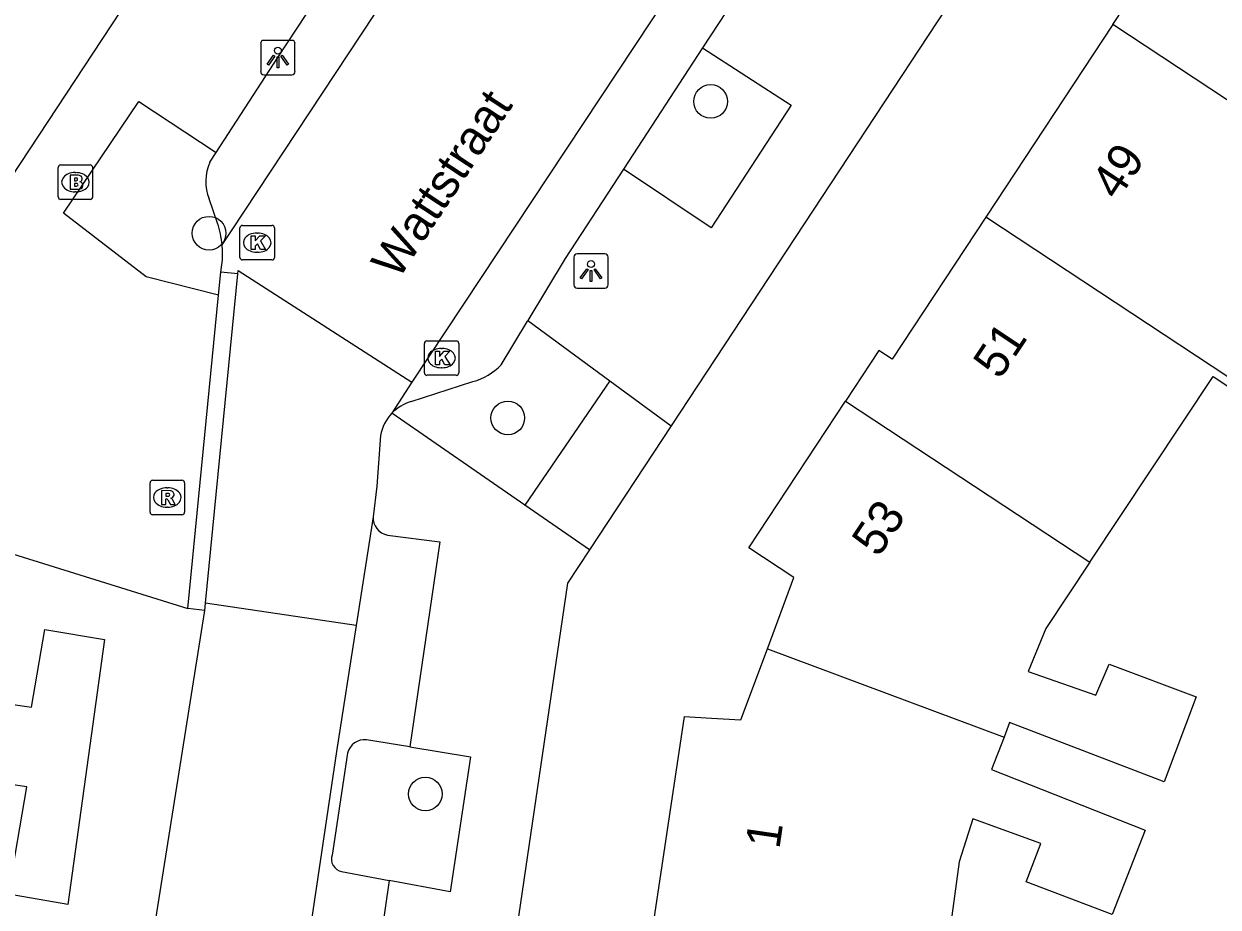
# Model space of a CAD drawing. Extents: x 159280 to 160375, y 384531 to 385872.
# Drawn here: x 159980.04 to 160014.71, y 384791.65 to 384817.27 of the extents above; entities that cross this region are included whole.
import ezdxf

# ---------------------------------------------------------------- set-up
doc = ezdxf.new("R2010")
doc.units = 0
for name, color, linetype in [('IMGEO_Boom', 7, 'Continuous'), ('IMGEO_Brandkraan', 7, 'Continuous'), ('IMGEO_Kolk', 7, 'Continuous'), ('IMGEO_Lichtpunt', 7, 'Continuous'), ('IMGEO_Openbare_ruimte_label', 7, 'Continuous'), ('IMGEO_Pand', 7, 'Continuous'), ('IMGEO_Pand_nummerreeks', 7, 'Continuous'), ('IMGEO_Parkeervlak_open', 7, 'Continuous'), ('IMGEO_Rijbaan_lokaal_open', 7, 'Continuous'), ('IMGEO_Rioolput', 7, 'Continuous'), ('IMGEO_Voetpad_open', 7, 'Continuous')]:
    doc.layers.add(name, color=color, linetype=linetype)

msp = doc.modelspace()

# ---------------------------------------------------------------- linework, layer by layer
at = {"layer": 'IMGEO_Boom'}
for centre in [(159999.976, 384815.022), (159985.419, 384811.2), (159994.089, 384805.84), (159991.696, 384794.928)]:
    msp.add_circle(centre, 0.489, dxfattribs=at)
at = {"layer": 'IMGEO_Brandkraan'}
for p, q in [((159981.039, 384812.253), (159981.039, 384813.105)), ((159981.114, 384813.179), (159981.966, 384813.179)), ((159982.04, 384813.105), (159982.04, 384812.253)), ((159981.527, 384812.959), (159981.552, 384812.959)), ((159981.55, 384812.399), (159981.525, 384812.399)), ((159981.966, 384812.179), (159981.114, 384812.179))]:
    msp.add_line(p, q, dxfattribs=at)
for points in [[(159981.039, 384812.253), (159981.039, 384813.105)], [(159981.114, 384813.179), (159981.966, 384813.179)], [(159982.04, 384813.105), (159982.04, 384812.253)], [(159981.387, 384812.879), (159981.387, 384812.479), (159981.6, 384812.479)], [(159981.618, 384812.879), (159981.387, 384812.879)], [(159981.566, 384812.798), (159981.512, 384812.798), (159981.512, 384812.722)], [(159981.512, 384812.722), (159981.565, 384812.722)], [(159981.574, 384812.646), (159981.512, 384812.646), (159981.512, 384812.565)], [(159981.512, 384812.565), (159981.574, 384812.565)], [(159981.966, 384812.179), (159981.114, 384812.179)]]:
    msp.add_lwpolyline(points, dxfattribs=at)
for centre, radius, start, end in [((159981.116, 384813.103), 0.0765, 91.552, 178.448), ((159981.116, 384813.103), 0.0765, 91.552, 178.448), ((159981.964, 384813.103), 0.0765, 1.552, 88.448), ((159981.964, 384813.103), 0.0765, 1.552, 88.448), ((159981.567, 384812.76), 0.0379, 267.8285, 90.9355), ((159981.622, 384812.734), 0.145, 59.4692, 91.5367), ((159981.647, 384812.781), 0.0922, 285.5137, 58.1501), ((159981.652, 384812.589), 0.105, 301.3115, 78.989), ((159981.575, 384812.605), 0.0404, 269.8759, 90.5077), ((159981.606, 384812.73), 0.251, 268.6676, 293.5347), ((159981.116, 384812.255), 0.0765, 181.552, 268.448), ((159981.116, 384812.255), 0.0765, 181.552, 268.448), ((159981.964, 384812.255), 0.0765, 271.552, 358.448), ((159981.964, 384812.255), 0.0765, 271.552, 358.448)]:
    msp.add_arc(centre, radius, start, end, dxfattribs=at)
for centre, major_axis, ratio, start_param, end_param in [((159981.526, 384812.679), (-0.387, 0.002), 0.722429, 4.712389, 7.853982), ((159981.551, 384812.679), (-0.39, 0.002), 0.717154, 1.570796, 4.712389)]:
    msp.add_ellipse(centre, major_axis=major_axis, ratio=ratio, start_param=start_param, end_param=end_param, dxfattribs=at)
at = {"layer": 'IMGEO_Kolk'}
for p, q in [((159986.315, 384810.499), (159986.315, 384811.351)), ((159986.39, 384811.425), (159987.242, 384811.425)), ((159987.316, 384811.351), (159987.316, 384810.499)), ((159986.803, 384811.205), (159986.828, 384811.205)), ((159986.826, 384810.645), (159986.801, 384810.645)), ((159987.242, 384810.425), (159986.39, 384810.425)), ((159991.667, 384807.15), (159991.667, 384808.002)), ((159991.742, 384808.076), (159992.594, 384808.076)), ((159992.155, 384807.856), (159992.18, 384807.856)), ((159992.668, 384808.002), (159992.668, 384807.15)), ((159992.178, 384807.296), (159992.153, 384807.296)), ((159992.594, 384807.076), (159991.742, 384807.076))]:
    msp.add_line(p, q, dxfattribs=at)
for points in [[(159986.315, 384810.499), (159986.315, 384811.351)], [(159986.39, 384811.425), (159987.242, 384811.425)], [(159987.316, 384811.351), (159987.316, 384810.499)], [(159986.636, 384811.125), (159986.759, 384811.125), (159986.759, 384810.974), (159986.889, 384811.125), (159987.053, 384811.125), (159986.907, 384810.974), (159987.06, 384810.725), (159986.908, 384810.725), (159986.823, 384810.889), (159986.759, 384810.822), (159986.759, 384810.725), (159986.636, 384810.725), (159986.636, 384811.125)], [(159987.242, 384810.425), (159986.39, 384810.425)], [(159991.667, 384807.15), (159991.667, 384808.002)], [(159991.742, 384808.076), (159992.594, 384808.076)], [(159992.668, 384808.002), (159992.668, 384807.15)], [(159991.988, 384807.776), (159992.111, 384807.776), (159992.111, 384807.625), (159992.241, 384807.776), (159992.405, 384807.776), (159992.259, 384807.625), (159992.412, 384807.376), (159992.26, 384807.376), (159992.175, 384807.54), (159992.111, 384807.473), (159992.111, 384807.376), (159991.988, 384807.376), (159991.988, 384807.776)], [(159992.594, 384807.076), (159991.742, 384807.076)]]:
    msp.add_lwpolyline(points, dxfattribs=at)
for centre, start, end in [((159986.392, 384811.349), 91.552, 178.448), ((159986.392, 384811.349), 91.552, 178.448), ((159987.24, 384811.349), 1.552, 88.448), ((159987.24, 384811.349), 1.552, 88.448), ((159986.392, 384810.501), 181.552, 268.448), ((159986.392, 384810.501), 181.552, 268.448), ((159987.24, 384810.501), 271.552, 358.448), ((159987.24, 384810.501), 271.552, 358.448), ((159991.744, 384808), 91.552, 178.448), ((159991.744, 384808), 91.552, 178.448), ((159992.592, 384808), 1.552, 88.448), ((159992.592, 384808), 1.552, 88.448), ((159991.744, 384807.152), 181.552, 268.448), ((159991.744, 384807.152), 181.552, 268.448), ((159992.592, 384807.152), 271.552, 358.448), ((159992.592, 384807.152), 271.552, 358.448)]:
    msp.add_arc(centre, 0.0765, start, end, dxfattribs=at)
for centre, major_axis, ratio, start_param, end_param in [((159986.802, 384810.925), (-0.387, 0.002), 0.722429, 4.712389, 7.853982), ((159986.827, 384810.925), (-0.39, 0.002), 0.717154, 1.570796, 4.712389), ((159992.154, 384807.576), (-0.387, 0.002), 0.722429, 4.712389, 7.853982), ((159992.179, 384807.576), (-0.39, 0.002), 0.717154, 1.570796, 4.712389)]:
    msp.add_ellipse(centre, major_axis=major_axis, ratio=ratio, start_param=start_param, end_param=end_param, dxfattribs=at)
at = {"layer": 'IMGEO_Lichtpunt'}
for p, q in [((159986.917, 384816.7), (159986.917, 384815.893)), ((159986.917, 384816.7), (159986.917, 384815.893)), ((159987.819, 384816.795), (159987.011, 384816.795)), ((159987.819, 384816.795), (159987.011, 384816.795)), ((159987.913, 384815.893), (159987.913, 384816.7)), ((159987.913, 384815.893), (159987.913, 384816.7)), ((159987.011, 384815.799), (159987.819, 384815.799)), ((159987.011, 384815.799), (159987.819, 384815.799)), ((159996.908, 384810.601), (159996.1, 384810.601)), ((159996.908, 384810.601), (159996.1, 384810.601)), ((159996.006, 384810.506), (159996.006, 384809.699)), ((159996.006, 384810.506), (159996.006, 384809.699)), ((159997.002, 384809.699), (159997.002, 384810.506)), ((159997.002, 384809.699), (159997.002, 384810.506)), ((159996.1, 384809.605), (159996.908, 384809.605)), ((159996.1, 384809.605), (159996.908, 384809.605))]:
    msp.add_line(p, q, dxfattribs=at)
for points in [[(159987.291, 384816.364), (159987.33, 384816.336), (159987.142, 384816.074), (159987.104, 384816.101), (159987.291, 384816.364)], [(159987.393, 384816.316), (159987.44, 384816.316), (159987.44, 384815.994), (159987.393, 384815.994), (159987.393, 384816.316)], [(159987.503, 384816.336), (159987.541, 384816.363), (159987.728, 384816.101), (159987.689, 384816.073), (159987.503, 384816.336)], [(159996.38, 384810.17), (159996.419, 384810.142), (159996.231, 384809.88), (159996.193, 384809.907), (159996.38, 384810.17)], [(159996.482, 384810.122), (159996.529, 384810.122), (159996.529, 384809.8), (159996.482, 384809.8), (159996.482, 384810.122)], [(159996.592, 384810.142), (159996.63, 384810.169), (159996.817, 384809.907), (159996.778, 384809.879), (159996.592, 384810.142)]]:
    msp.add_lwpolyline(points, dxfattribs=at)
for centre in [(159987.416, 384816.498), (159996.505, 384810.304)]:
    msp.add_circle(centre, 0.0994, dxfattribs=at)
for centre, start, end in [((159987.011, 384816.7), 90, 180), ((159987.011, 384816.7), 90, 180), ((159987.819, 384816.7), 0, 90), ((159987.819, 384816.7), 0, 90), ((159987.011, 384815.893), 180, 270), ((159987.011, 384815.893), 180, 270), ((159987.819, 384815.893), 270, 0), ((159987.819, 384815.893), 270, 360), ((159996.1, 384810.506), 90, 180), ((159996.1, 384810.506), 90, 180), ((159996.908, 384810.506), 0, 90), ((159996.908, 384810.506), 0, 90), ((159996.1, 384809.699), 180, 270), ((159996.1, 384809.699), 180, 270), ((159996.908, 384809.699), 270, 0), ((159996.908, 384809.699), 270, 360)]:
    msp.add_arc(centre, 0.0946, start, end, dxfattribs=at)
at = {"layer": 'IMGEO_Pand'}
for points in [[(160011.647, 384817.255), (160015.335, 384822.844)], [(159985.221, 384821.252), (159979.412, 384812.432)], [(160011.647, 384817.255), (160007.96, 384811.666)], [(160018.277, 384812.882), (160011.647, 384817.255)], [(160007.96, 384811.666), (160005.241, 384807.545), (160004.859, 384807.797), (160003.891, 384806.33)], [(160018.769, 384804.537), (160007.96, 384811.666)], [(160010.982, 384801.651), (160014.564, 384807.039), (160016.262, 384805.919), (160015.654, 384804.997), (160018.036, 384803.426), (160018.285, 384803.804)], [(160001.624, 384799.14), (160002.393, 384801.207), (160001.082, 384802.072), (160003.891, 384806.33)], [(160003.891, 384806.33), (160010.982, 384801.651)], [(160010.982, 384801.651), (160009.702, 384799.726), (160009.198, 384798.484), (160011.159, 384797.792), (160011.545, 384798.693), (160014.067, 384797.745), (160013.139, 384795.283), (160008.655, 384797.003), (160008.492, 384796.58)], [(159998.616, 384790.404), (159998.212, 384790.464), (159999.218, 384797.174), (160000, 384797.128), (160000.856, 384797.076), (160001.624, 384799.14)], [(160001.624, 384799.14), (160008.492, 384796.58)], [(160008.492, 384796.58), (160008.131, 384795.641), (160012.586, 384793.881), (160011.627, 384791.429), (160009.135, 384792.377), (160009.56, 384793.488), (160007.588, 384794.21), (160007.194, 384792.959), (160006.673, 384789.191)]]:
    msp.add_lwpolyline(points, dxfattribs=at)
at = {"layer": 'IMGEO_Parkeervlak_open'}
for points in [[(159999.745, 384816.574), (159997.448, 384813.057)], [(159985.44, 384813.257), (159985.621, 384813.537)], [(159985.668, 384811.493), (159985.419, 384812.197)], [(159993.894, 384807.378), (159994.661, 384808.649), (159994.67, 384808.665)], [(159991.281, 384806.316), (159993.079, 384806.893)], [(159991.246, 384796.299), (159989.988, 384796.501)], [(159989.434, 384796.111), (159988.989, 384793.158)], [(159989.265, 384792.681), (159990.644, 384792.421)]]:
    msp.add_lwpolyline(points, dxfattribs=at)
for centre, radius, start, end in [((159986.693, 384812.702), 1.371, 156.113, 201.617), ((159982.859, 384810.592), 2.95, 5.1775, 17.7892), ((159992.569, 384808.677), 1.856, 285.9514, 315.5617), ((159991.653, 384805.08), 1.291, 106.755, 136.0459), ((159989.935, 384795.987), 0.517, 84.1651, 166.1238), ((159989.334, 384793.039), 0.365, 160.9501, 259.1586)]:
    msp.add_arc(centre, radius, start, end, dxfattribs=at)
at = {"layer": 'IMGEO_Rijbaan_lokaal_open'}
for points in [[(159985.797, 384810.858), (159986.069, 384811.27), (160006.068, 384841.522), (160006.412, 384842.044)], [(160012.164, 384838.368), (159991.303, 384806.873)], [(159985.757, 384810.067), (159985.805, 384810.429)], [(159985.318, 384800.469), (159986.254, 384810.018)], [(159986.254, 384810.018), (159985.757, 384810.067)], [(159986.254, 384810.018), (159986.263, 384810.122), (159991.303, 384806.873)], [(159991.303, 384806.873), (159990.724, 384805.976)], [(159990.392, 384805.329), (159990.285, 384803.857), (159990.179, 384802.974)], [(159990.179, 384802.974), (159989.688, 384799.82)], [(159983.639, 384789.836), (159985.298, 384800.257)], [(159985.298, 384800.257), (159985.318, 384800.469)], [(159989.688, 384799.82), (159985.318, 384800.469)], [(159989.688, 384799.82), (159989.119, 384796.166), (159974.741, 384699.469)]]:
    msp.add_lwpolyline(points, dxfattribs=at)
for centre, radius, start, end in [((159982.932, 384810.59), 2.878, 356.793, 5.3437), ((159991.644, 384805.095), 1.274, 136.2492, 169.4227)]:
    msp.add_arc(centre, radius, start, end, dxfattribs=at)
at = {"layer": 'IMGEO_Rioolput'}
for p, q in [((159983.781, 384804.031), (159984.633, 384804.031)), ((159983.706, 384803.105), (159983.706, 384803.957)), ((159984.194, 384803.811), (159984.219, 384803.811)), ((159984.707, 384803.957), (159984.707, 384803.105)), ((159984.633, 384803.031), (159983.781, 384803.031)), ((159984.217, 384803.251), (159984.192, 384803.251))]:
    msp.add_line(p, q, dxfattribs=at)
for points in [[(159983.781, 384804.031), (159984.633, 384804.031)], [(159983.706, 384803.105), (159983.706, 384803.957)], [(159984.295, 384803.729), (159984.043, 384803.731), (159984.043, 384803.331)], [(159984.707, 384803.957), (159984.707, 384803.105)], [(159984.043, 384803.331), (159984.167, 384803.331), (159984.167, 384803.493), (159984.178, 384803.493)], [(159984.221, 384803.65), (159984.167, 384803.65), (159984.167, 384803.569)], [(159984.167, 384803.569), (159984.219, 384803.569)], [(159984.225, 384803.464), (159984.296, 384803.331), (159984.436, 384803.331), (159984.371, 384803.457)], [(159984.633, 384803.031), (159983.781, 384803.031)]]:
    msp.add_lwpolyline(points, dxfattribs=at)
for centre, radius, start, end in [((159983.783, 384803.955), 0.0765, 91.552, 178.448), ((159983.783, 384803.955), 0.0765, 91.552, 178.448), ((159984.631, 384803.955), 0.0765, 1.552, 88.448), ((159984.631, 384803.955), 0.0765, 1.552, 88.448), ((159984.294, 384803.619), 0.109, 350.3612, 89.416), ((159984.177, 384803.44), 0.0533, 26.0293, 88.6989), ((159984.203, 384803.758), 0.19, 274.7715, 282.9687), ((159984.227, 384803.554), 0.0964, 77.0061, 93.1865), ((159984.241, 384803.611), 0.0378, 276.6634, 79.6772), ((159984.292, 384803.619), 0.112, 277.5842, 350.9817), ((159984.276, 384803.404), 0.108, 29.5134, 73.7905), ((159983.783, 384803.107), 0.0765, 181.552, 268.448), ((159983.783, 384803.107), 0.0765, 181.552, 268.448), ((159984.631, 384803.107), 0.0765, 271.552, 358.448), ((159984.631, 384803.107), 0.0765, 271.552, 358.448)]:
    msp.add_arc(centre, radius, start, end, dxfattribs=at)
for centre, major_axis, ratio, start_param, end_param in [((159984.193, 384803.531), (-0.387, 0.002), 0.722429, 4.712389, 7.853982), ((159984.218, 384803.531), (-0.39, 0.002), 0.717154, 1.570796, 4.712389)]:
    msp.add_ellipse(centre, major_axis=major_axis, ratio=ratio, start_param=start_param, end_param=end_param, dxfattribs=at)
at = {"layer": 'IMGEO_Voetpad_open'}
for points in [[(160019.155, 384836.479), (159998.831, 384805.608)], [(160003.366, 384822.119), (160001.134, 384818.701), (159999.745, 384816.574)], [(159985.621, 384813.537), (159987.41, 384816.297), (159989.077, 384818.834)], [(159999.745, 384816.574), (160002.313, 384814.919), (159999.99, 384811.357), (159997.448, 384813.057)], [(159985.692, 384809.4), (159983.594, 384809.937), (159981.195, 384811.781), (159983.377, 384815.023), (159985.621, 384813.537)], [(159997.448, 384813.057), (159995.757, 384810.467), (159994.67, 384808.665)], [(159985.692, 384809.4), (159985.757, 384810.067)], [(159984.8, 384800.306), (159985.692, 384809.4)], [(159994.67, 384808.665), (159997.055, 384806.913)], [(159997.055, 384806.913), (159994.584, 384803.31)], [(159997.055, 384806.913), (159998.831, 384805.608)], [(159994.584, 384803.31), (159990.724, 384805.976)], [(159998.831, 384805.608), (159996.464, 384802.013)], [(159973.437, 384803.848), (159984.8, 384800.306)], [(159996.464, 384802.013), (159994.584, 384803.31)], [(159990.599, 384802.442), (159992.12, 384802.244), (159991.246, 384796.299)], [(159996.464, 384802.013), (159995.827, 384801.045), (159988.319, 384750), (159986.258, 384735.984)], [(159985.298, 384800.257), (159984.8, 384800.306)], [(159980.126, 384795.133), (159972.287, 384796.274), (159972.726, 384798.542), (159980.267, 384797.447), (159980.654, 384799.704), (159982.388, 384799.407), (159981.318, 384791.722), (159979.593, 384792.018), (159980.126, 384795.133)], [(159991.246, 384796.299), (159993.004, 384796.007), (159992.42, 384792.092), (159990.644, 384792.421)], [(159990.644, 384792.421), (159989.788, 384786.475)]]:
    msp.add_lwpolyline(points, dxfattribs=at)
msp.add_arc((159990.693, 384802.948), 0.515, 177.099, 259.4813, dxfattribs=at)

# ---------------------------------------------------------------- texts
at = {"layer": 'IMGEO_Openbare_ruimte_label'}
msp.add_text('Wattstraat', height=1, rotation=56.7072, dxfattribs=at).set_placement((159990.909, 384809.825))
at = {"layer": 'IMGEO_Pand_nummerreeks'}
for s, rotation, p in [('49', 56.4249, (160011.793, 384812.119)), ('51', 56.4249, (160008.37, 384806.924)), ('53', 56.4221, (160004.848, 384801.765)), ('1', 81.726, (160001.971, 384793.31))]:
    msp.add_text(s, height=1, rotation=rotation, dxfattribs=at).set_placement(p)

doc.saveas('drawing.dxf')
